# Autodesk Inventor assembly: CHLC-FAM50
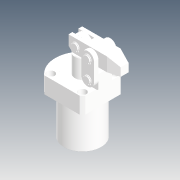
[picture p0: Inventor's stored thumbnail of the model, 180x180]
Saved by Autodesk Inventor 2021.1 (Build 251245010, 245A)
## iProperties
Company: Microsoft
Created: 2019-11
Part Number: CHLC-FAM50
Description: STEP AP214
Document SubType Name: Assembly
Designer: user
Title: CHLC-FAM50.STEP
Author: Windows
Revision Number: ÈÎºÎ
Sending System: SolidWorks 2015
Preprocessor: SwSTEP 2.0
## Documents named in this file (9)
- D:\Vault_2016\Projekty\Clamptek\Hydraulic\CHLC\CHLC-50\Inventor\CHLC-FAM50\CHLC-FAM50.iam
- D:\Vault_2016\Projekty\Clamptek\Hydraulic\CHLC\CHLC-50\Inventor\CHLC-FAM50\CHLC-50-01.ipt
- D:\Vault_2016\Projekty\Clamptek\Hydraulic\CHLC\CHLC-50\Inventor\CHLC-FAM50\CHLC-50-02.ipt
- D:\Vault_2016\Projekty\Clamptek\Hydraulic\CHLC\CHLC-50\Inventor\CHLC-FAM50\CHLC-50-03.ipt
- D:\Vault_2016\Projekty\Clamptek\Hydraulic\CHLC\CHLC-50\Inventor\CHLC-FAM50\CHLC-50-04.ipt
- D:\Vault_2016\Projekty\Clamptek\Hydraulic\CHLC\CHLC-50\Inventor\CHLC-FAM50\CHLC-50-06.ipt
- D:\Vault_2016\Projekty\Clamptek\Hydraulic\CHLC\CHLC-50\Inventor\CHLC-FAM50\CHLC-50-09.ipt
- D:\Vault_2016\Projekty\Clamptek\Hydraulic\CHLC\CHLC-50\Inventor\CHLC-FAM50\CHLC-FAM50-01.ipt
- D:\Vault_2016\Projekty\Clamptek\Hydraulic\CHLC\CHLC-50\Inventor\CHLC-FAM50\M6LS.ipt
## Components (18 placed, 18 different names)
1. CHLC-50-01_1
2. CHLC-50-02_2
3. CHLC-50-03_3
4. CHLC-50-04_4
5. CHLC-50-06_5
6. CHLC-50-09_6
7. CHLC-FAM50-01_7
8. M6LS_8
9. M6LS_9
10. M6LS_10
11. CHLC-50-04_11
12. CHLC-50-03_12
13. CHLC-50-06_13
14. CHLC-50-06_14
15. CHLC-50-06_15
16. CHLC-50-06_16
17. CHLC-50-06_17
18. M6LS_18
